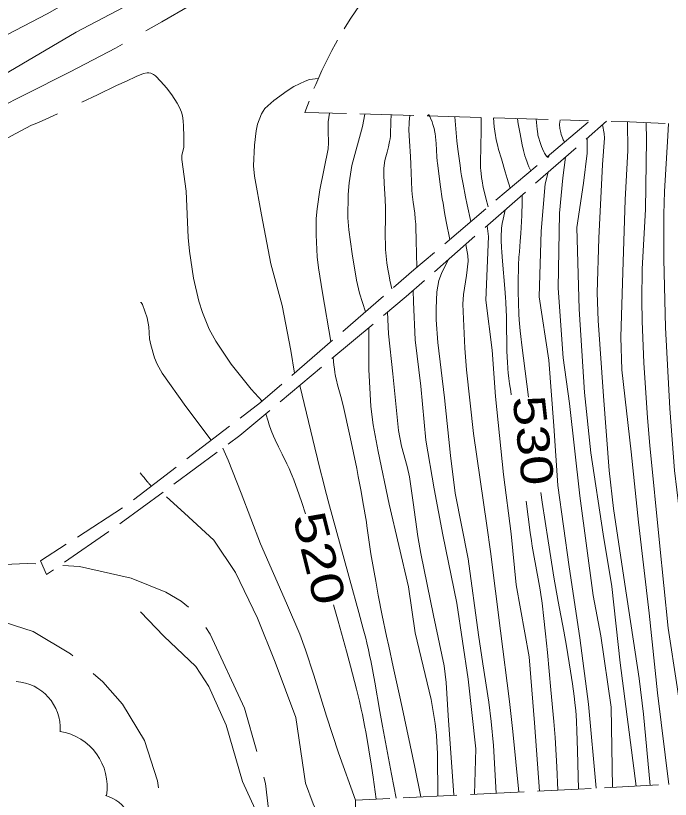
# Model space of a CAD drawing. Extents: x 2361284 to 2366480, y 6976556 to 6985346.
# Drawn here: x 2364281.2 to 2364378.6, y 6978605.3 to 6978721.9 of the extents above; entities that cross this region are included whole.
import ezdxf
from ezdxf.enums import TextEntityAlignment as Align

# ---------------------------------------------------------------- set-up
doc = ezdxf.new("R2010")
doc.units = 0
doc.header["$LTSCALE"] = 1.9
for name, color, linetype, lineweight in [('12', 7, 'Continuous', 13), ('13', 7, 'Continuous', 13), ('15', 7, 'Continuous', 13), ('16', 7, 'Continuous', 13), ('20', 7, 'Continuous', 13), ('22', 7, 'Continuous', 13), ('24', 7, 'Continuous', 13), ('6', 7, 'Continuous', 13)]:
    doc.layers.add(name, color=color, linetype=linetype, lineweight=lineweight)

msp = doc.modelspace()

# ---------------------------------------------------------------- linework, layer by layer
at = {"layer": '12'}
for points in [[(2364339.84, 6978707.059), (2364339.743, 6978706.12), (2364339.713, 6978705.651), (2364339.704, 6978705.182), (2364339.71, 6978704.947), (2364339.799, 6978703.241), (2364339.938, 6978700.967), (2364339.998, 6978699.83), (2364340.155, 6978695.981), (2364340.198, 6978695.369), (2364340.237, 6978694.962), (2364340.335, 6978694.148), (2364340.557, 6978692.524), (2364340.652, 6978691.711), (2364340.719, 6978690.896), (2364340.737, 6978690.487), (2364340.792, 6978688.488), (2364340.874, 6978684.488)], [(2364355.845, 6978706.591), (2364355.958, 6978705.837), (2364356.226, 6978704.334), (2364356.434, 6978703.228), (2364356.548, 6978702.681), (2364356.74, 6978701.865), (2364356.965, 6978701.055), (2364357.093, 6978700.651), (2364357.282, 6978700.114), (2364357.385, 6978699.845), (2364357.551, 6978699.443), (2364357.829, 6978698.839)], [(2364372.241, 6978706.107), (2364372.251, 6978701.867), (2364371.891, 6978694.502), (2364371.534, 6978683.749), (2364371.209, 6978674.082), (2364371.391, 6978669.256), (2364372.768, 6978657.01), (2364373.877, 6978646.579), (2364375.436, 6978633.054), (2364376.669, 6978621.174), (2364378.378, 6978607.571)], [(2364306.213, 6978702.369), (2364305.913, 6978701.129), (2364305.89, 6978700.506), (2364306.555, 6978695.792), (2364306.85, 6978688.934), (2364307.048, 6978686.903), (2364307.658, 6978682.862), (2364308.448, 6978679.437), (2364308.985, 6978677.764), (2364310, 6978675.304), (2364310.973, 6978673.477), (2364313.27, 6978670.073), (2364316.234, 6978666.336), (2364317.853, 6978664.567)], [(2364356.563, 6978695.237), (2364356.541, 6978694.223), (2364356.482, 6978692.195), (2364356.447, 6978691.308), (2364356.336, 6978689.536), (2364356.247, 6978688.355), (2364356.127, 6978686.78), (2364356.074, 6978685.993), (2364356.009, 6978684.812), (2364355.987, 6978684.221), (2364355.954, 6978682.733), (2364355.947, 6978681.989), (2364355.95, 6978680.872), (2364355.986, 6978679.195), (2364356.059, 6978677.519), (2364356.111, 6978676.682), (2364356.246, 6978675.01), (2364356.329, 6978674.175), (2364356.475, 6978672.925), (2364357.479, 6978665.164)], [(2364340.327, 6978681.042), (2364340.393, 6978679.323), (2364340.617, 6978673.715), (2364341.482, 6978666.802), (2364342.229, 6978658.759), (2364343.478, 6978651.551), (2364344.754, 6978644.692), (2364346.81, 6978634.532), (2364348.528, 6978623.207), (2364349.657, 6978612.847), (2364349.471, 6978606.096)], [(2364318.41, 6978662.693), (2364318.74, 6978661.581), (2364318.921, 6978661.03), (2364319.214, 6978660.211), (2364319.547, 6978659.381), (2364319.788, 6978658.835), (2364320.298, 6978657.756), (2364320.832, 6978656.687), (2364321.541, 6978655.262), (2364321.88, 6978654.543), (2364322.201, 6978653.816), (2364322.352, 6978653.449), (2364322.565, 6978652.892), (2364323.362, 6978650.642), (2364323.744, 6978649.511), (2364324.293, 6978647.807)], [(2364359.334, 6978650.972), (2364359.53, 6978649.537), (2364359.948, 6978646.671), (2364360.392, 6978643.808), (2364361.316, 6978638.089), (2364361.502, 6978636.98), (2364361.903, 6978634.769), (2364362.745, 6978630.352), (2364363.141, 6978628.137), (2364363.556, 6978625.654), (2364363.754, 6978624.411), (2364364.032, 6978622.544), (2364364.277, 6978620.674), (2364364.385, 6978619.737), (2364364.509, 6978618.487), (2364364.562, 6978617.861), (2364364.63, 6978616.922), (2364364.701, 6978615.51), (2364364.794, 6978612.621), (2364364.844, 6978610.695), (2364364.924, 6978606.843)], [(2364328.461, 6978634.277), (2364329.154, 6978631.864), (2364330.417, 6978627.38), (2364331.031, 6978625.133), (2364331.624, 6978622.88), (2364331.91, 6978621.749), (2364332.338, 6978619.95), (2364332.603, 6978618.747), (2364332.771, 6978617.944), (2364333.09, 6978616.333), (2364333.314, 6978615.122), (2364333.733, 6978612.695), (2364334.118, 6978610.261), (2364334.363, 6978608.637), (2364334.836, 6978605.386)]]:
    msp.add_lwpolyline(points, dxfattribs=at)
at = {"layer": '13'}
for points in [[(2364320.846, 6978741.031), (2364317.59, 6978739.54), (2364310.146, 6978735.718), (2364301.969, 6978731.13), (2364295.123, 6978727.505), (2364285.873, 6978722.206), (2364276.399, 6978717.277), (2364262.941, 6978709.688), (2364252.425, 6978703.897), (2364240.292, 6978696.902), (2364227.251, 6978690.538), (2364214.992, 6978683.981), (2364202.477, 6978677.171), (2364186.695, 6978668.74), (2364170.8, 6978660.879), (2364156.681, 6978653.385), (2364138.204, 6978643.408), (2364121.923, 6978633.953), (2364110.521, 6978627.734), (2364094.521, 6978619.291), (2364075.604, 6978609.261), (2364063.636, 6978602.807), (2364048.497, 6978595.203), (2364040.513, 6978590.407)], [(2364301.264, 6978725.323), (2364290.21, 6978719.437), (2364278.454, 6978712.585), (2364264.992, 6978705.397), (2364245.94, 6978695.915), (2364230.683, 6978687.12), (2364211.127, 6978677.274), (2364191.552, 6978667.116), (2364174.308, 6978657.983), (2364160.441, 6978650.12), (2364138.84, 6978638.584), (2364124.005, 6978630.643), (2364117.793, 6978627.583), (2364100.712, 6978619.27), (2364088.197, 6978612.321), (2364078.027, 6978606.854), (2364068.178, 6978601.63), (2364061.939, 6978598.331), (2364053.285, 6978594.358)], [(2364326.207, 6978712.569), (2364324.916, 6978712.4), (2364324.271, 6978712.181), (2364322.591, 6978711.359), (2364321.564, 6978710.735), (2364319.587, 6978709.296), (2364318.257, 6978708.09), (2364317.756, 6978707.329), (2364317.175, 6978705.798), (2364316.948, 6978704.762), (2364316.73, 6978702.659), (2364316.593, 6978699.557), (2364316.725, 6978698.019), (2364317.749, 6978692.297), (2364319.178, 6978684.991), (2364320.858, 6978678.787), (2364322.148, 6978672.111), (2364322.684, 6978668.753)], [(2364327.906, 6978707.415), (2364327.698, 6978706.143), (2364327.677, 6978704.79), (2364327.746, 6978702.987), (2364327.686, 6978702.093), (2364326.434, 6978696.011), (2364326.029, 6978693.164), (2364325.915, 6978691.735), (2364325.878, 6978689.299), (2364326.068, 6978686.046), (2364326.264, 6978684.429), (2364326.84, 6978680.674), (2364328.089, 6978673.426)], [(2364333.157, 6978707.255), (2364332.815, 6978705.422), (2364331.21, 6978699.626), (2364330.793, 6978697.042), (2364330.645, 6978695.313), (2364330.624, 6978691.859), (2364330.761, 6978690.06), (2364331.235, 6978686.466), (2364331.91, 6978682.556), (2364332.365, 6978680.634), (2364333.227, 6978677.875)], [(2364337.039, 6978707.142), (2364337.018, 6978706.158), (2364336.947, 6978704.191), (2364336.935, 6978703.991), (2364336.893, 6978703.593), (2364336.831, 6978703.197), (2364336.779, 6978702.935), (2364336.659, 6978702.411), (2364336.454, 6978701.628), (2364336.187, 6978700.585), (2364336.078, 6978700.061), (2364335.999, 6978699.534), (2364335.974, 6978699.27), (2364335.957, 6978698.871), (2364335.961, 6978698.255), (2364336.007, 6978697.023), (2364336.155, 6978694.557), (2364336.2, 6978693.323), (2364336.206, 6978692.715), (2364336.2, 6978691.5), (2364336.181, 6978689.879), (2364336.18, 6978689.068), (2364336.202, 6978687.853), (2364336.239, 6978687.115), (2364336.276, 6978686.625), (2364336.375, 6978685.646), (2364336.437, 6978685.158), (2364336.583, 6978684.184), (2364336.754, 6978683.212), (2364336.88, 6978682.565), (2364337.155, 6978681.272)], [(2364342.51, 6978706.984), (2364342.527, 6978707.067), (2364342.541, 6978707.107), (2364342.576, 6978707.154), (2364342.596, 6978707.161), (2364342.643, 6978707.147), (2364342.696, 6978707.096), (2364342.735, 6978707.044), (2364342.819, 6978706.9), (2364342.92, 6978706.684), (2364343.133, 6978706.13), (2364343.27, 6978705.709), (2364343.432, 6978705.14), (2364343.498, 6978704.872), (2364343.572, 6978704.515), (2364343.595, 6978704.364), (2364343.651, 6978703.874), (2364343.729, 6978702.893), (2364343.848, 6978700.933), (2364343.908, 6978700.282), (2364343.947, 6978699.957), (2364344.412, 6978696.434), (2364344.669, 6978694.674), (2364344.776, 6978694), (2364345.004, 6978692.655), (2364345.25, 6978691.313), (2364345.776, 6978688.634)], [(2364346.513, 6978706.862), (2364346.611, 6978705.669), (2364346.837, 6978703.285), (2364346.974, 6978702.068), (2364347.301, 6978699.639), (2364347.436, 6978698.704), (2364347.534, 6978698.083), (2364347.747, 6978696.843), (2364348.103, 6978694.99), (2364348.36, 6978693.758), (2364348.911, 6978691.294)], [(2364350.464, 6978706.75), (2364350.442, 6978704.849), (2364350.358, 6978700.058), (2364350.37, 6978699.317), (2364350.4, 6978698.824), (2364350.428, 6978698.496), (2364350.504, 6978697.842), (2364350.577, 6978697.353), (2364350.758, 6978696.378), (2364350.977, 6978695.405), (2364351.139, 6978694.758), (2364351.49, 6978693.468)], [(2364352.285, 6978706.697), (2364352.406, 6978705.397), (2364352.482, 6978704.749), (2364352.576, 6978704.102), (2364352.632, 6978703.78), (2364352.702, 6978703.422), (2364352.865, 6978702.712), (2364353.049, 6978702.008), (2364353.452, 6978700.608), (2364354.024, 6978698.669), (2364354.319, 6978697.703), (2364354.783, 6978696.26)], [(2364358.656, 6978706.508), (2364358.729, 6978705.539), (2364358.778, 6978705.055), (2364358.866, 6978704.33), (2364358.898, 6978704.139), (2364359.006, 6978703.689), (2364359.162, 6978703.179), (2364359.421, 6978702.467), (2364359.563, 6978702.122), (2364359.782, 6978701.648), (2364359.891, 6978701.44), (2364360.047, 6978701.177), (2364360.176, 6978701.005), (2364360.235, 6978700.943), (2364360.317, 6978700.886), (2364360.366, 6978700.872), (2364360.389, 6978700.874), (2364360.42, 6978700.887), (2364360.456, 6978700.924), (2364360.472, 6978700.952), (2364360.493, 6978701.006), (2364360.517, 6978701.115)], [(2364362.197, 6978706.401), (2364362.13, 6978706.032), (2364362.113, 6978705.846), (2364362.108, 6978705.566), (2364362.129, 6978705.288), (2364362.149, 6978705.151), (2364362.232, 6978704.733), (2364362.282, 6978704.525), (2364362.37, 6978704.217), (2364362.532, 6978703.761), (2364362.664, 6978703.463), (2364362.738, 6978703.316), (2364362.858, 6978703.097)], [(2364374.992, 6978705.993), (2364375.067, 6978703.444), (2364374.895, 6978693.09), (2364374.399, 6978684.256), (2364374.352, 6978679.594), (2364374.395, 6978676.484), (2364374.652, 6978670.267), (2364375.194, 6978662.075), (2364375.549, 6978657.986), (2364376.977, 6978643.508), (2364378.267, 6978630.821), (2364379.61, 6978622.102), (2364381.637, 6978607.742)], [(2364378.324, 6978705.855), (2364378.201, 6978704.023), (2364377.73, 6978695.749), (2364377.621, 6978692.405), (2364377.605, 6978685.717), (2364377.852, 6978675.539), (2364378.517, 6978663.465), (2364379.215, 6978654.241), (2364379.886, 6978648.513), (2364380.97, 6978640.897), (2364381.418, 6978637.08), (2364381.76, 6978632.682), (2364382.079, 6978626.805), (2364382.262, 6978623.867), (2364382.941, 6978616.664), (2364383.411, 6978613.088), (2364384.285, 6978607.887)], [(2364368.505, 6978705.681), (2364368.77, 6978704.366), (2364368.794, 6978703.704), (2364368.521, 6978699.761), (2364367.965, 6978688.835), (2364367.705, 6978680.671), (2364367.832, 6978676.594), (2364368.649, 6978665.3), (2364369.474, 6978654.268), (2364370.117, 6978648.615), (2364371.825, 6978637.359), (2364373.948, 6978623.308), (2364374.594, 6978618.023), (2364375.61, 6978607.424)], [(2364366.224, 6978703.679), (2364366.225, 6978701.439), (2364365.656, 6978697.004), (2364364.659, 6978690.404), (2364365.005, 6978678.247), (2364365.812, 6978665.873), (2364366.759, 6978656.902), (2364368.624, 6978644.809), (2364369.868, 6978636.98), (2364371.146, 6978625.642), (2364373.511, 6978607.304)], [(2364362.99, 6978700.859), (2364362.589, 6978697.785), (2364362.079, 6978692.529), (2364361.885, 6978681.357), (2364362.633, 6978671.033), (2364363.598, 6978664.232), (2364365.109, 6978650.466), (2364367.121, 6978635.645), (2364368.258, 6978629.665), (2364369.809, 6978619.029), (2364369.992, 6978607.121)], [(2364360.441, 6978698.624), (2364359.977, 6978696.91), (2364359.384, 6978689.834), (2364359.087, 6978680.071), (2364360.496, 6978670.673), (2364361.25, 6978660.89), (2364361.864, 6978652.016), (2364363.549, 6978639.94), (2364365.12, 6978629.346), (2364366.404, 6978619.516), (2364367.573, 6978606.988)], [(2364354.004, 6978693.002), (2364353.805, 6978692.104), (2364353.713, 6978691.655), (2364353.591, 6978690.982), (2364353.493, 6978690.307), (2364353.456, 6978689.97), (2364353.408, 6978689.294), (2364353.4, 6978688.955), (2364353.408, 6978688.447), (2364353.462, 6978687.43), (2364353.508, 6978686.752), (2364353.617, 6978685.397), (2364353.984, 6978681.328), (2364354.084, 6978679.972), (2364354.124, 6978679.293), (2364354.176, 6978678.035), (2364354.199, 6978677.196), (2364354.225, 6978675.515), (2364354.254, 6978673.273), (2364354.279, 6978672.153), (2364354.321, 6978671.034), (2364354.35, 6978670.475), (2364354.429, 6978669.358), (2364354.479, 6978668.801), (2364354.572, 6978667.966), (2364354.686, 6978667.146), (2364354.855, 6978666.055), (2364354.935, 6978665.509)], [(2364351.337, 6978690.667), (2364351.522, 6978689.069), (2364351.122, 6978679.585), (2364352.093, 6978672.163), (2364352.559, 6978665.257), (2364353.759, 6978653.639), (2364354.902, 6978644.838), (2364355.634, 6978637.235), (2364357.566, 6978626.533), (2364358.389, 6978616.73), (2364359.136, 6978606.568)], [(2364348.173, 6978687.897), (2364348.463, 6978686.219), (2364348.497, 6978685.38), (2364348.279, 6978683.255), (2364347.812, 6978680.421), (2364347.738, 6978679.003), (2364347.999, 6978672.477), (2364348.271, 6978669.216), (2364349.331, 6978659.747), (2364351.271, 6978646.064), (2364351.858, 6978642.199), (2364353.33, 6978630.404), (2364354.669, 6978619.905), (2364355.181, 6978615.415), (2364356.037, 6978606.418)], [(2364345.555, 6978685.612), (2364344.532, 6978683.554), (2364344.157, 6978682.496), (2364343.849, 6978680.856), (2364343.745, 6978678.339), (2364343.768, 6978676.658), (2364344.022, 6978673.307), (2364345.01, 6978665.085), (2364345.892, 6978656.504), (2364346.585, 6978650.9), (2364348.498, 6978641.107), (2364350.036, 6978629.792), (2364350.691, 6978625.504), (2364351.58, 6978619.788), (2364351.958, 6978616.919), (2364352.292, 6978613.371), (2364352.68, 6978606.256)], [(2364299.762, 6978679.246), (2364299.861, 6978679.258), (2364300.08, 6978678.943), (2364300.734, 6978676.966), (2364300.99, 6978675.629), (2364301.12, 6978673.846), (2364301.282, 6978672.971), (2364301.866, 6978671.027), (2364302.235, 6978670.085), (2364302.962, 6978668.755), (2364306.52, 6978663.779), (2364310.297, 6978658.766)], [(2364336.488, 6978677.796), (2364336.648, 6978674.607), (2364337.305, 6978668.622), (2364338.125, 6978660.2), (2364338.584, 6978657.886), (2364339.44, 6978654.844), (2364339.781, 6978653.306), (2364340.345, 6978649.508), (2364341.034, 6978644.431), (2364341.479, 6978641.91), (2364343.367, 6978632.669), (2364344.929, 6978625.182), (2364345.241, 6978622.731), (2364345.55, 6978617.798), (2364346.402, 6978605.946)], [(2364333.759, 6978675.52), (2364333.758, 6978669.288), (2364334.044, 6978663.798), (2364334.387, 6978661.065), (2364335.099, 6978657.105), (2364336.759, 6978649.256), (2364339.646, 6978636.933), (2364340.641, 6978630.123), (2364343.016, 6978620.204), (2364343.583, 6978616.62), (2364343.785, 6978614.82), (2364343.933, 6978612.112), (2364344.013, 6978605.833)], [(2364328.451, 6978671.078), (2364328.543, 6978669.947), (2364328.603, 6978669.383), (2364328.679, 6978668.82), (2364328.725, 6978668.54), (2364328.828, 6978668.018), (2364328.906, 6978667.672), (2364329.081, 6978666.986), (2364329.662, 6978664.941), (2364329.839, 6978664.256), (2364329.919, 6978663.911), (2364330.947, 6978659.235), (2364331.447, 6978656.894), (2364331.928, 6978654.548), (2364332.16, 6978653.373), (2364332.587, 6978651.11), (2364332.859, 6978649.6), (2364333.374, 6978646.574), (2364333.455, 6978646.051), (2364333.601, 6978645.003), (2364333.876, 6978642.905), (2364334.039, 6978641.86), (2364334.518, 6978639.136), (2364334.765, 6978637.776), (2364335.146, 6978635.737), (2364335.742, 6978632.683), (2364336.366, 6978629.636), (2364336.69, 6978628.114), (2364337.355, 6978625.073), (2364338.25, 6978621.021), (2364338.687, 6978618.993), (2364340.561, 6978610.139), (2364341.483, 6978605.709)], [(2364323.452, 6978666.9), (2364325.126, 6978660.127), (2364325.724, 6978657.646), (2364326.516, 6978654.336), (2364326.926, 6978652.684), (2364327.243, 6978651.449), (2364327.896, 6978648.982), (2364329.912, 6978641.6), (2364330.911, 6978637.976), (2364332.253, 6978633.147), (2364332.915, 6978630.729), (2364333.277, 6978629.336), (2364333.447, 6978628.637), (2364333.687, 6978627.585), (2364333.907, 6978626.529), (2364334.01, 6978625.999), (2364334.606, 6978622.748), (2364335.384, 6978618.412), (2364335.783, 6978616.245), (2364337.125, 6978609.103), (2364337.805, 6978605.534)], [(2364311.999, 6978657.582), (2364312.796, 6978655.799), (2364314.743, 6978650.888), (2364317.594, 6978643.363), (2364321.509, 6978634.511), (2364323.447, 6978629.905), (2364324.326, 6978627.567), (2364325.551, 6978623.808), (2364327.448, 6978617.716), (2364329.231, 6978612.243), (2364331.767, 6978605.236)], [(2364299.703, 6978653.905), (2364299.744, 6978653.856), (2364299.798, 6978653.791), (2364299.825, 6978653.758), (2364299.907, 6978653.66), (2364300.069, 6978653.463), (2364300.286, 6978653.201), (2364300.395, 6978653.07), (2364300.504, 6978652.939), (2364300.558, 6978652.874), (2364300.631, 6978652.787), (2364300.668, 6978652.743), (2364300.723, 6978652.678), (2364300.805, 6978652.581), (2364300.879, 6978652.495), (2364300.916, 6978652.451), (2364300.971, 6978652.387), (2364301.027, 6978652.322), (2364301.055, 6978652.29), (2364301.111, 6978652.226), (2364301.139, 6978652.194), (2364301.181, 6978652.146), (2364301.237, 6978652.082), (2364301.265, 6978652.05), (2364301.308, 6978652.002), (2364301.372, 6978651.931)], [(2364303.637, 6978650.332), (2364306.301, 6978647.896), (2364310.649, 6978643.887), (2364313.885, 6978639.068), (2364317.179, 6978632.29), (2364319.802, 6978625.724), (2364322.891, 6978617.513), (2364324.294, 6978607.725), (2364325.443, 6978604.676), (2364328.61, 6978597.596), (2364331.703, 6978584.645), (2364334.691, 6978571.203), (2364337.217, 6978554.785), (2364338.866, 6978542.321), (2364341.843, 6978523.709), (2364343.159, 6978509.379), (2364344.602, 6978492.332), (2364346.462, 6978474.509), (2364349.618, 6978457.008), (2364351.866, 6978443.638), (2364354.387, 6978423.561)], [(2364357.146, 6978649.71), (2364357.74, 6978645.025), (2364357.918, 6978643.807), (2364358.051, 6978642.996), (2364358.339, 6978641.379), (2364358.946, 6978638.149), (2364359.228, 6978636.531), (2364359.396, 6978635.45), (2364359.472, 6978634.908), (2364359.574, 6978634.093), (2364359.73, 6978632.71), (2364360.025, 6978629.943), (2364360.301, 6978627.174), (2364360.823, 6978621.633), (2364361.262, 6978616.906), (2364361.45, 6978614.539), (2364361.611, 6978611.925), (2364361.699, 6978610.181), (2364361.845, 6978606.693)], [(2364299.75, 6978633.244), (2364303.214, 6978629.627), (2364307.987, 6978625.091), (2364309.926, 6978622.14), (2364312.521, 6978616.354), (2364314.93, 6978608.016), (2364320.107, 6978596.765), (2364323.978, 6978585.251), (2364327.597, 6978574.705), (2364331.452, 6978560.62), (2364334.411, 6978545.959), (2364336.789, 6978530.42), (2364338.96, 6978510.38), (2364340.687, 6978488.575), (2364342.98, 6978469.355), (2364345.429, 6978456.919), (2364350.076, 6978424.7)]]:
    msp.add_lwpolyline(points, dxfattribs=at)
at = {"layer": '15'}
for points in [[(2364284.201, 6978640.356), (2364282.91, 6978640.433), (2364271.524, 6978639.905), (2364265.853, 6978638.991), (2364264.347, 6978638.557)], [(2364306.894, 6978633.912), (2364305.825, 6978634.822), (2364303.522, 6978636.169), (2364298.391, 6978638.241), (2364290.675, 6978639.977), (2364288.194, 6978640.124)], [(2364271.081, 6978631.752), (2364274.246, 6978632.382), (2364278.049, 6978632.128), (2364283.807, 6978630.323), (2364289.339, 6978626.984), (2364289.692, 6978626.677)], [(2364317.048, 6978612.467), (2364315.246, 6978618.92), (2364310.142, 6978629.903), (2364309.492, 6978630.907)], [(2364292.717, 6978624.066), (2364294.138, 6978622.839), (2364297.08, 6978619.517), (2364300.381, 6978614.118), (2364302.269, 6978608.096), (2364302.429, 6978607.069)], [(2364319.594, 6978588.71), (2364319.276, 6978600.017), (2364318.383, 6978607.709), (2364318.125, 6978608.617)]]:
    msp.add_lwpolyline(points, dxfattribs=at)
at = {"layer": '16'}
for centre, radius, start, end in [((2364280.846, 6978615.896), 6.973, 356.77443, 86.77443), ((2364286.447, 6978607.196), 8.364, 351.00838, 81.00838), ((2364293.112, 6978600.513), 5.573, 344.77323, 74.77323)]:
    msp.add_arc(centre, radius, start, end, dxfattribs=at)
at = {"layer": '20'}
for points in [[(2364324.889, 6978733.478), (2364324.233, 6978733.052), (2364321.387, 6978731.484), (2364318.541, 6978729.917), (2364314.871, 6978727.812), (2364311.191, 6978725.707), (2364307.053, 6978723.358), (2364302.915, 6978721.008), (2364300.548, 6978719.646)], [(2364297.067, 6978717.674), (2364296.052, 6978717.094), (2364289.306, 6978713.559), (2364282.488, 6978710.154), (2364275.002, 6978706.372), (2364272.136, 6978704.925)]]:
    msp.add_lwpolyline(points, dxfattribs=at)
at = {"layer": '22'}
for points in [[(2364291.019, 6978709.025), (2364293.358, 6978710.137), (2364296.215, 6978711.504), (2364297.658, 6978712.178), (2364299.102, 6978712.842), (2364300.189, 6978713.292), (2364300.748, 6978713.397), (2364301.017, 6978713.41), (2364301.278, 6978713.362), (2364301.71, 6978713.177), (2364302.002, 6978712.959), (2364302.81, 6978712.127), (2364303.639, 6978711.155), (2364304.409, 6978710.142), (2364305.241, 6978708.9), (2364305.587, 6978708.243), (2364305.863, 6978707.546), (2364305.998, 6978707.027), (2364306.116, 6978706.248), (2364306.163, 6978705.468), (2364306.188, 6978703.919), (2364306.213, 6978702.369)], [(2364262.352, 6978694.831), (2364263.517, 6978695.363), (2364265.847, 6978696.455), (2364270.137, 6978698.476), (2364274.387, 6978700.576), (2364276.665, 6978701.838), (2364278.934, 6978703.14), (2364281.232, 6978704.401), (2364283.561, 6978705.604), (2364284.348, 6978705.941), (2364285.135, 6978706.269), (2364287.395, 6978707.32)]]:
    msp.add_lwpolyline(points, dxfattribs=at)
at = {"layer": '24'}
for p, q in [((2364340.41, 6978707.054), (2364332.417, 6978707.288)), ((2364350.404, 6978706.759), (2364342.41, 6978706.993)), ((2364360.396, 6978706.464), (2364352.405, 6978706.698)), ((2364360.289, 6978700.923), (2364366.391, 6978706.091)), ((2364366.399, 6978706.281), (2364362.397, 6978706.403)), ((2364369.1, 6978706.197), (2364366.084, 6978703.568)), ((2364364.576, 6978702.254), (2364358.556, 6978696.986)), ((2364352.651, 6978694.459), (2364358.761, 6978699.628)), ((2364357.049, 6978695.672), (2364351.029, 6978690.404)), ((2364345.022, 6978687.997), (2364351.123, 6978693.164)), ((2364349.522, 6978689.09), (2364343.501, 6978683.823)), ((2364329.854, 6978674.952), (2364335.905, 6978680.19)), ((2364334.374, 6978676.025), (2364328.233, 6978670.896)), ((2364322.297, 6978668.409), (2364328.347, 6978673.648)), ((2364326.695, 6978669.611), (2364320.554, 6978664.482)), ((2364306.654, 6978655.971), (2364313.008, 6978660.832)), ((2364311.184, 6978656.984), (2364304.739, 6978652.243)), ((2364298.71, 6978649.894), (2364305.065, 6978654.756)), ((2364290.383, 6978644.365), (2364297.102, 6978648.709)), ((2364295.036, 6978645.179), (2364288.449, 6978640.636))]:
    msp.add_line(p, q, dxfattribs=at)
for points in [[(2364330.086, 6978719.977), (2364330.47, 6978720.61), (2364331.071, 6978721.556), (2364331.693, 6978722.482), (2364332.324, 6978723.408), (2364332.975, 6978724.324), (2364333.637, 6978725.221), (2364334.328, 6978726.107), (2364334.664, 6978726.53)], [(2364325.571, 6978711.073), (2364325.825, 6978711.696), (2364326.275, 6978712.72), (2364326.736, 6978713.734), (2364327.216, 6978714.749), (2364327.716, 6978715.754), (2364328.237, 6978716.74), (2364328.768, 6978717.725), (2364329.073, 6978718.258)], [(2364330.416, 6978707.349), (2364324.226, 6978707.52), (2364324.596, 6978708.574), (2364324.839, 6978709.216)], [(2364377.804, 6978705.87), (2364372.531, 6978706.1), (2364369.81, 6978706.174)], [(2364337.413, 6978681.495), (2364340.448, 6978684.124), (2364343.493, 6978686.703)], [(2364341.993, 6978682.508), (2364339.295, 6978680.142), (2364335.912, 6978677.31)], [(2364314.596, 6978662.047), (2364317.625, 6978664.365), (2364320.789, 6978667.105)], [(2364319.016, 6978663.199), (2364314.541, 6978659.456), (2364312.793, 6978658.169)], [(2364303.13, 6978651.057), (2364296.894, 6978646.457), (2364296.685, 6978646.315)], [(2364286.8, 6978639.5), (2364285.766, 6978638.781), (2364284.907, 6978640.832), (2364288.704, 6978643.279)]]:
    msp.add_lwpolyline(points, dxfattribs=at)
at = {"layer": '6'}
for p, q in [((2364376.809, 6978607.486), (2364368.823, 6978607.06)), ((2364346.852, 6978605.96), (2364338.864, 6978605.574)), ((2364356.837, 6978606.446), (2364348.851, 6978606.06))]:
    msp.add_line(p, q, dxfattribs=at)
for points in [[(2364366.824, 6978606.951), (2364364.864, 6978606.842), (2364358.836, 6978606.545)], [(2364336.865, 6978605.475), (2364331.767, 6978605.236), (2364331.812, 6978602.647), (2364332.122, 6978602.66)]]:
    msp.add_lwpolyline(points, dxfattribs=at)

# ---------------------------------------------------------------- texts
at = {"layer": '12'}
for s, rotation, width, p in [(' 530 ', 276.32, 1.25, (2364355.839, 6978658.474)), (' 520 ', 284.083, 1.3, (2364324.073, 6978640.637))]:
    msp.add_text(s, height=4.799, rotation=rotation, dxfattribs=dict(at, width=width)).set_placement(p, align=Align.CENTER)

doc.saveas('drawing.dxf')
